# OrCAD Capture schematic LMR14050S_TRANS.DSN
size Custom; title: 40V, 3.5A SIMPLE SWITCHER®, 2.2MHz Step-Down Regulator; note: DATASHEET:
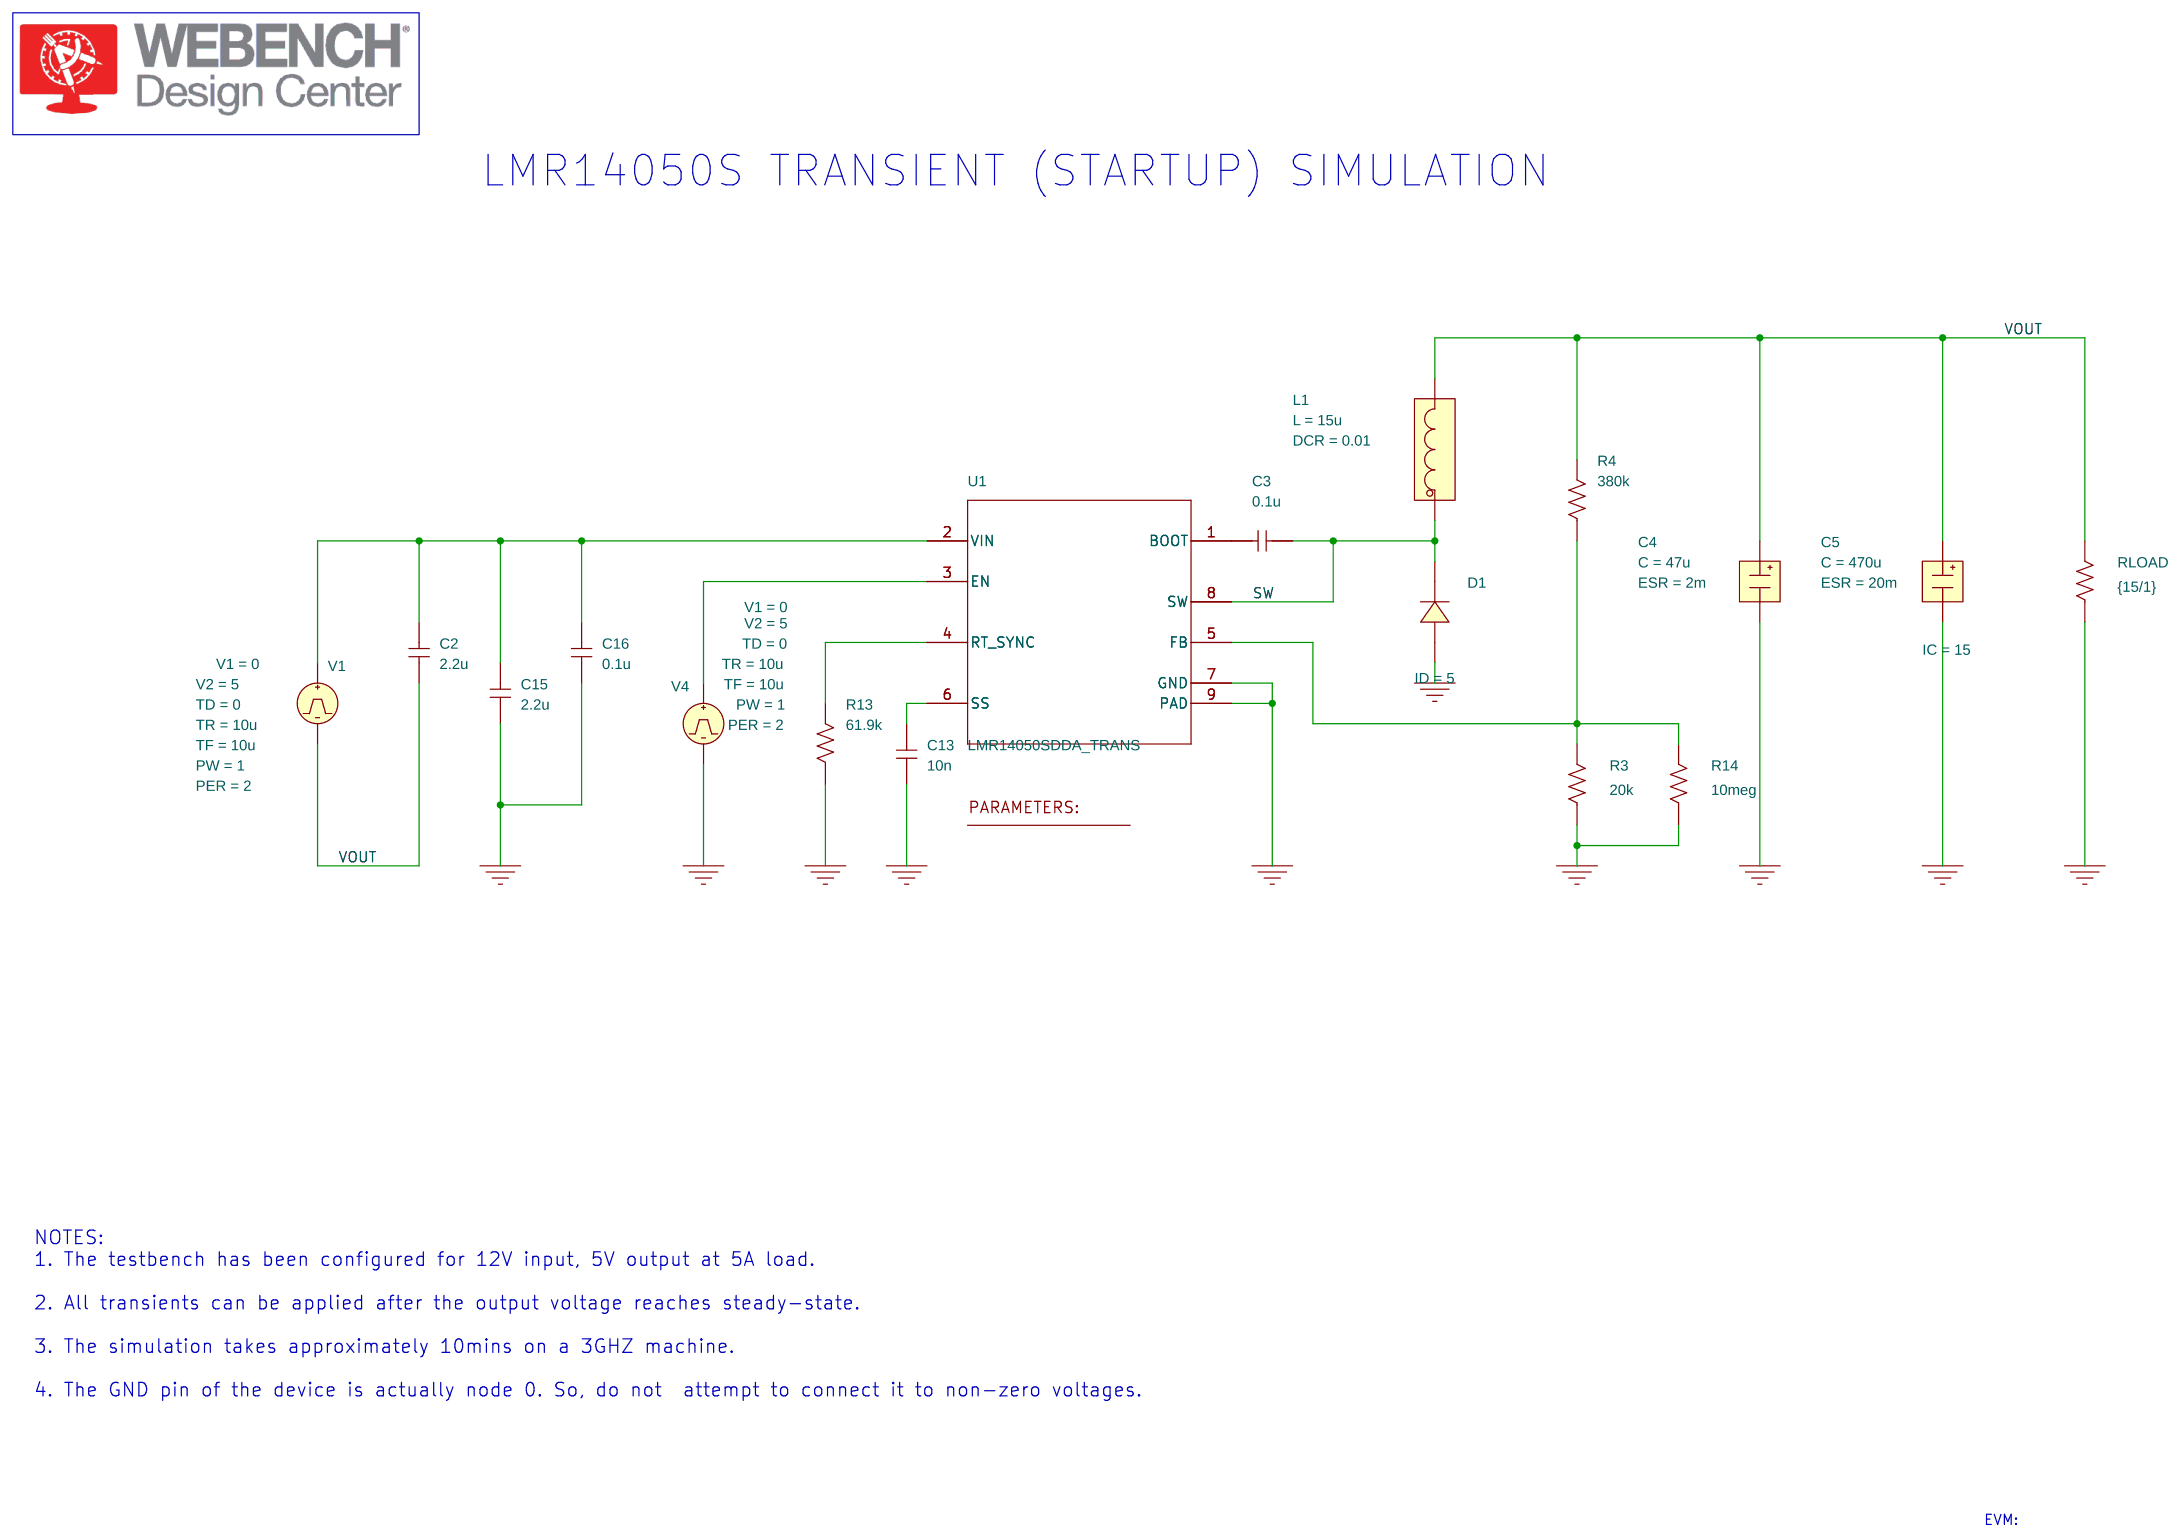
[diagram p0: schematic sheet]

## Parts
1  PARAM
C2  2.2u  [RAD/CK05]
C3  0.1u  [RAD/CK05]
C4  CESR
C5  CESR
C13  10n  [RAD/CK05]
C15  2.2u  [RAD/CK05]
C16  0.1u  [RAD/CK05]
D1  D_D1
L1  LDCR
R3  20k  [AX/RC05]
R4  380k  [AX/RC05]
R13  61.9k  [AX/RC05]
R14  10meg  [AX/RC05]
RLOAD  {15/1}  [AX/RC05]
U1  LMR14050SDDA_TRANS  [DDA0008E]
V1  VPULSE
V4  VPULSE

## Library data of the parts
1 = PARAM
C2 C3 C15 C16 = C
C4 = CESR: C: 47u; ESR: 2m; IC: 15; ID: 0; PSpiceTemplate: X^@REFDES %IN %OUT @MODEL PARAMS:  ?C|C=@C||C=100u|  ?ESR|ESR=@ESR||ESR=0.01| ?X|X=@X||X=2|  ?IC|IC=@IC||IC=2|; X: 1
C5 = CESR: C: 470u; ESR: 20m; IC: 15; ID: 0; PSpiceTemplate: X^@REFDES %IN %OUT @MODEL PARAMS:  ?C|C=@C||C=100u|  ?ESR|ESR=@ESR||ESR=0.01| ?X|X=@X||X=2|  ?IC|IC=@IC||IC=2|; X: 1
C13 = C: IC: 5
D1 = D_D1
L1 = LDCR: DCR: 0.01; IC: 0; ID: 5; L: 15u; PSpiceTemplate: X^@REFDES %IN %OUT @MODEL PARAMS:  ?L|L=@L||L=1u|  ?DCR|DCR=@DCR||DCR=0.01| ?IC|IC=@IC||IC=0|
R3 R4 R13 R14 RLOAD = R
U1 = LMR14050SDDA_TRANS: PSpiceTemplate: X^@REFDES %BOOT %VIN %EN %RT_SYNC %FB %SS %GND %SW %PAD @MODEL
V1 V4 = VPULSE: PER: 2; PW: 1; TD: 0; TF: 10u; TR: 10u; V1: 0; V2: 5

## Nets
0: C4.3(OUT) C5.3(OUT) C13.1 C15.1 C16.1 D1.2(A) R3.1 R13.1 R14.1 RLOAD.1 U1.7(GND) U1.9(PAD) V4.2(-)
SW: C3.1 D1.1(C) L1.1(IN) U1.8(SW)
VOUT: C2.1 C4.1(IN) C5.1(IN) L1.3(OUT) R4.2 RLOAD.2 V1.2(-)
N7516999: C13.2 U1.6(SS)
N7517009: U1.3(EN) V4.1(+)
N7517075: C2.2 C15.2 C16.2 U1.2(VIN) V1.1(+)
N7517151: R3.2 R4.1 R14.2 U1.5(FB)
N14557517: R13.2 U1.4(RT_SYNC)
N14565855: C3.2 U1.1(BOOT)

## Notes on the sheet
- LMR14050S TRANSIENT (STARTUP) SIMULATION
- NOTES:
  1. The testbench has been configured for 12V input, 5V output at 5A load.
  2. All transients can be applied after the output voltage reaches steady-state.
  3. The simulation takes approximately 10mins on a 3GHZ machine.
  4. The GND pin of the device is actually node 0. So, do not  attempt to connect it to non-zero voltages.
- EVM:
